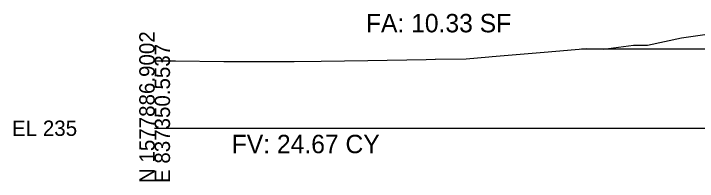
# Model space of a CAD drawing. Extents: x -26 to 303, y -16 to 6048.
# Drawn here: x -25.7 to 98.9, y 3490.3 to 3520.9 of the extents above; entities that cross this region are included whole.
import ezdxf

# ---------------------------------------------------------------- set-up
doc = ezdxf.new("R2010")
doc.units = 0
for name, color, linetype in [('CONST_DCH', 7, 'Continuous'), ('Draft_XS_Grid', 7, 'Continuous'), ('DTM_X_GROUND', 7, 'Continuous'), ('XS_CELL', 7, 'Continuous'), ('XS_P_GROUND', 7, 'Continuous'), ('XS_SHEET_EW_TX_AREA', 7, 'Continuous'), ('XS_SHEET_EW_TX_VOLUME', 7, 'Continuous')]:
    doc.layers.add(name, color=color, linetype=linetype)

msp = doc.modelspace()

# ---------------------------------------------------------------- linework, layer by layer
at = {"layer": 'DTM_X_GROUND'}
msp.add_lwpolyline([(0, 3512.28), (3.8, 3512.27), (12.59, 3512.2), (18.79, 3512.2), (25.44, 3512.19), (30.32, 3512.26), (38.83, 3512.39), (49.46, 3512.55), (51.13, 3512.62), (51.2, 3512.62), (56.79, 3512.67), (60.9, 3513.01), (61.51, 3513.08), (70.97, 3513.9), (78.76, 3514.57), (81.81, 3514.41), (87.3, 3515.14), (89.8, 3515.16), (96.02, 3516.5), (102.4, 3517.39)], dxfattribs=at)
msp.add_lwpolyline([(0, 3512.28), (3.8, 3512.27), (12.59, 3512.2), (18.79, 3512.2), (25.44, 3512.19), (30.32, 3512.26), (38.83, 3512.39), (49.46, 3512.55), (51.13, 3512.62), (51.2, 3512.62), (56.79, 3512.67), (60.9, 3513.01), (61.51, 3513.08), (70.97, 3513.9), (78.76, 3514.57), (81.81, 3514.41), (87.3, 3515.14), (89.8, 3515.16), (96.02, 3516.5), (102.4, 3517.39)], dxfattribs=at)
at = {"layer": 'XS_CELL'}
msp.add_line((0, 3500), (150, 3500), dxfattribs=at)
at = {"layer": 'XS_P_GROUND'}
msp.add_lwpolyline([(77.77, 3514.47), (79.01, 3514.48), (84.01, 3514.49), (84.1, 3514.49), (89.19, 3514.49), (94.29, 3514.5), (99.38, 3514.5), (102.26, 3514.51)], dxfattribs=at)

# ---------------------------------------------------------------- texts
at = {"layer": 'CONST_DCH'}
msp.add_text('X', height=0.24, dxfattribs=at).set_placement((77.7, 3514.35))
at = {"layer": 'Draft_XS_Grid'}
msp.add_text('-', height=0.0001, dxfattribs=at).set_placement((0, 3500))
at = {"layer": 'XS_CELL'}
for s, p in [('N 1577886.9002', (0, 3490)), ('E 837350.5537', (2.8, 3490))]:
    msp.add_text(s, height=2.8, rotation=90, dxfattribs=at).set_placement(p)
msp.add_text('EL 235', height=2.8, dxfattribs=at).set_placement((-26, 3498.6))
at = {"layer": 'XS_SHEET_EW_TX_AREA'}
msp.add_text('FA: 10.33 SF', height=3.36, dxfattribs=at).set_placement((38.51, 3517.5))
at = {"layer": 'XS_SHEET_EW_TX_VOLUME'}
msp.add_text('FV: 24.67 CY', height=3.36, dxfattribs=at).set_placement((14.05, 3495.44))

doc.saveas('drawing.dxf')
